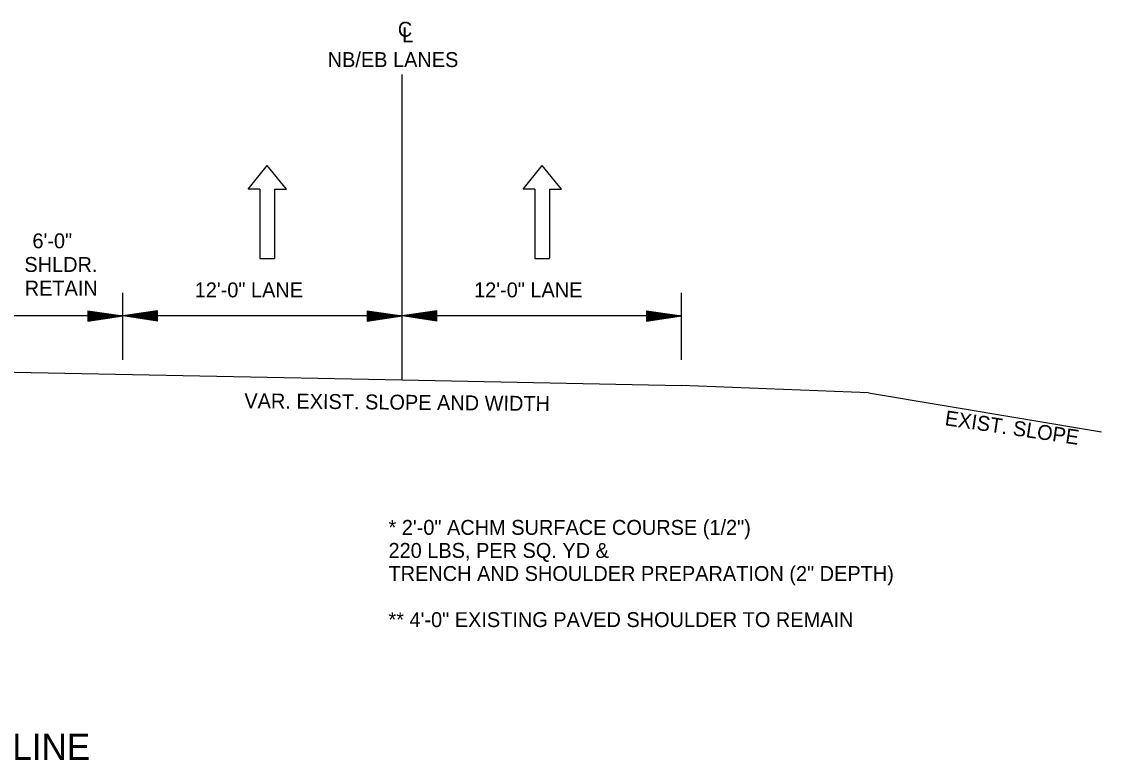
# Model space of a CAD drawing. Extents: x 1641422 to 1649187, y 577497 to 580642.
# Drawn here: x 1644249 to 1645119, y 577528 to 578123 of the extents above; entities that cross this region are included whole.
import ezdxf

# ---------------------------------------------------------------- set-up
doc = ezdxf.new("R2010")
doc.units = 0
doc.layers.add('R_Border', color=7, linetype='Continuous')
doc.layers.add('R_Draft', color=7, linetype='Continuous')

msp = doc.modelspace()

# ---------------------------------------------------------------- linework, layer by layer
at = {"layer": 'R_Draft'}
for p, q in [((1644555.43, 577904.55), (1644555.43, 578080.3)), ((1644440.95, 577988.14), (1644440.95, 577932.09)), ((1644452.69, 577988.14), (1644452.69, 577932.09)), ((1644662.46, 577988.14), (1644662.46, 577932.09)), ((1644674.2, 577988.14), (1644674.2, 577932.09)), ((1644440.95, 577932.09), (1644452.69, 577932.09)), ((1644662.46, 577932.09), (1644674.2, 577932.09)), ((1644330.46, 577850.7), (1644330.46, 577904.55)), ((1644555.43, 577850.7), (1644555.43, 577904.55)), ((1644780.4, 577850.7), (1644780.4, 577904.55)), ((1644330.46, 577886.01), (1644217.96, 577886.01)), ((1644302.34, 577890.22), (1644330.46, 577886.01)), ((1644302.34, 577890.22), (1644302.34, 577881.79)), ((1644302.34, 577889.52), (1644325.76, 577886.01)), ((1644302.34, 577888.8), (1644320.93, 577886.01)), ((1644302.34, 577888.1), (1644316.24, 577886.01)), ((1644302.34, 577887.37), (1644311.48, 577886.01)), ((1644302.34, 577886.67), (1644306.78, 577886.01)), ((1644302.34, 577881.79), (1644330.46, 577886.01)), ((1644302.34, 577884.63), (1644311.48, 577886.01)), ((1644302.34, 577883.21), (1644320.93, 577886.01)), ((1644302.34, 577882.49), (1644325.76, 577886.01)), ((1644302.34, 577883.91), (1644316.24, 577886.01)), ((1644302.34, 577885.35), (1644306.78, 577886.01)), ((1644555.43, 577886.01), (1644330.43, 577886.01)), ((1644358.59, 577890.22), (1644330.46, 577886.01)), ((1644358.59, 577881.79), (1644330.46, 577886.01)), ((1644358.59, 577889.52), (1644335.16, 577886.01)), ((1644358.59, 577882.49), (1644335.16, 577886.01)), ((1644358.59, 577888.8), (1644339.99, 577886.01)), ((1644358.59, 577883.21), (1644339.99, 577886.01)), ((1644358.59, 577888.1), (1644344.68, 577886.01)), ((1644358.59, 577883.91), (1644344.68, 577886.01)), ((1644358.59, 577887.38), (1644349.44, 577886.01)), ((1644358.59, 577884.64), (1644349.44, 577886.01)), ((1644358.59, 577886.67), (1644354.14, 577886.01)), ((1644358.59, 577885.35), (1644354.14, 577886.01)), ((1644358.59, 577881.79), (1644358.59, 577890.22)), ((1644527.3, 577890.22), (1644555.43, 577886.01)), ((1644527.3, 577890.22), (1644527.3, 577881.79)), ((1644527.3, 577889.52), (1644550.73, 577886.01)), ((1644527.3, 577888.8), (1644545.89, 577886.01)), ((1644527.3, 577888.1), (1644541.21, 577886.01)), ((1644527.3, 577887.37), (1644536.44, 577886.01)), ((1644527.3, 577886.67), (1644531.75, 577886.01)), ((1644527.3, 577881.79), (1644555.43, 577886.01)), ((1644527.3, 577884.63), (1644536.44, 577886.01)), ((1644527.3, 577883.21), (1644545.89, 577886.01)), ((1644527.3, 577882.49), (1644550.73, 577886.01)), ((1644527.3, 577883.91), (1644541.21, 577886.01)), ((1644527.3, 577885.35), (1644531.75, 577886.01)), ((1644780.4, 577886.01), (1644555.4, 577886.01)), ((1644583.55, 577890.22), (1644555.43, 577886.01)), ((1644583.55, 577881.79), (1644555.43, 577886.01)), ((1644583.55, 577889.52), (1644560.13, 577886.01)), ((1644583.55, 577882.49), (1644560.13, 577886.01)), ((1644583.55, 577888.8), (1644564.96, 577886.01)), ((1644583.55, 577883.21), (1644564.96, 577886.01)), ((1644583.55, 577888.1), (1644569.65, 577886.01)), ((1644583.55, 577883.91), (1644569.65, 577886.01)), ((1644583.55, 577887.38), (1644574.41, 577886.01)), ((1644583.55, 577884.64), (1644574.41, 577886.01)), ((1644583.55, 577886.67), (1644579.11, 577886.01)), ((1644583.55, 577885.35), (1644579.11, 577886.01)), ((1644583.55, 577881.79), (1644583.55, 577890.22)), ((1644752.27, 577890.22), (1644780.4, 577886.01)), ((1644752.27, 577890.22), (1644752.27, 577881.79)), ((1644752.27, 577889.52), (1644775.7, 577886.01)), ((1644752.27, 577888.8), (1644770.86, 577886.01)), ((1644752.27, 577888.1), (1644766.18, 577886.01)), ((1644752.27, 577887.37), (1644761.41, 577886.01)), ((1644752.27, 577886.67), (1644756.72, 577886.01)), ((1644752.27, 577881.79), (1644780.4, 577886.01)), ((1644752.27, 577884.63), (1644761.41, 577886.01)), ((1644752.27, 577883.21), (1644770.86, 577886.01)), ((1644752.27, 577882.49), (1644775.7, 577886.01)), ((1644752.27, 577883.91), (1644766.18, 577886.01)), ((1644752.27, 577885.35), (1644756.72, 577886.01)), ((1644555.43, 577834.56), (1644555.43, 577850.7)), ((1644217.96, 577841.31), (1644555.46, 577834.56)), ((1644555.43, 577834.56), (1644780.43, 577830.06)), ((1644930.92, 577824.04), (1644780.43, 577830.06)), ((1644930.92, 577824.04), (1645118.55, 577792.77))]:
    msp.add_line(p, q, dxfattribs=at)
for points in [[(1644440.95, 577988.14), (1644431.37, 577988.14), (1644446.82, 578006.96)], [(1644452.69, 577988.14), (1644462.27, 577988.14), (1644446.82, 578006.96)], [(1644662.46, 577988.14), (1644652.88, 577988.14), (1644668.33, 578006.96)], [(1644674.2, 577988.14), (1644683.78, 577988.14), (1644668.33, 578006.96)]]:
    msp.add_lwpolyline(points, dxfattribs=at)

# ---------------------------------------------------------------- texts
at = {"layer": 'R_Border'}
for s, p in [('* 2\'-0" ACHM SURFACE COURSE (1/2")', (1644544.5, 577709.8)), ('220 LBS, PER SQ. YD &', (1644544.5, 577691.24)), ('TRENCH AND SHOULDER PREPARATION (2" DEPTH)', (1644544.5, 577672.67)), ('** 4\'-0" EXISTING PAVED SHOULDER TO REMAIN', (1644544.5, 577635.55))]:
    msp.add_text(s, height=12, dxfattribs=at).set_placement(p)
at = {"layer": 'R_Draft'}
for s, height, p in [('C', 12, (1644552.03, 578110.7)), ('L', 12, (1644555.48, 578106.26)), ('NB/EB LANES', 12, (1644495.52, 578086.3)), ('6\'-0"', 12, (1644257.78, 577940.44)), ('SHLDR.', 12, (1644251.31, 577921.41)), ('RETAIN', 12, (1644251.55, 577902.38)), ('12\'-0" LANE', 12, (1644388.44, 577900.94)), ('12\'-0" LANE', 12, (1644613.41, 577900.94)), ('FOR WIRE ROPE SAFETY FENCE LEFT OF CENTERLINE', 21.0938, (1643544.2, 577528.56))]:
    msp.add_text(s, height=height, dxfattribs=at).set_placement(p)
for s, rotation, p in [('VAR. EXIST. SLOPE AND WIDTH', 359.4463, (1644428.37, 577811.78)), ('EXIST. SLOPE', 351.57554, (1644991.95, 577798.12))]:
    msp.add_text(s, height=12, rotation=rotation, dxfattribs=at).set_placement(p)

doc.saveas('drawing.dxf')
